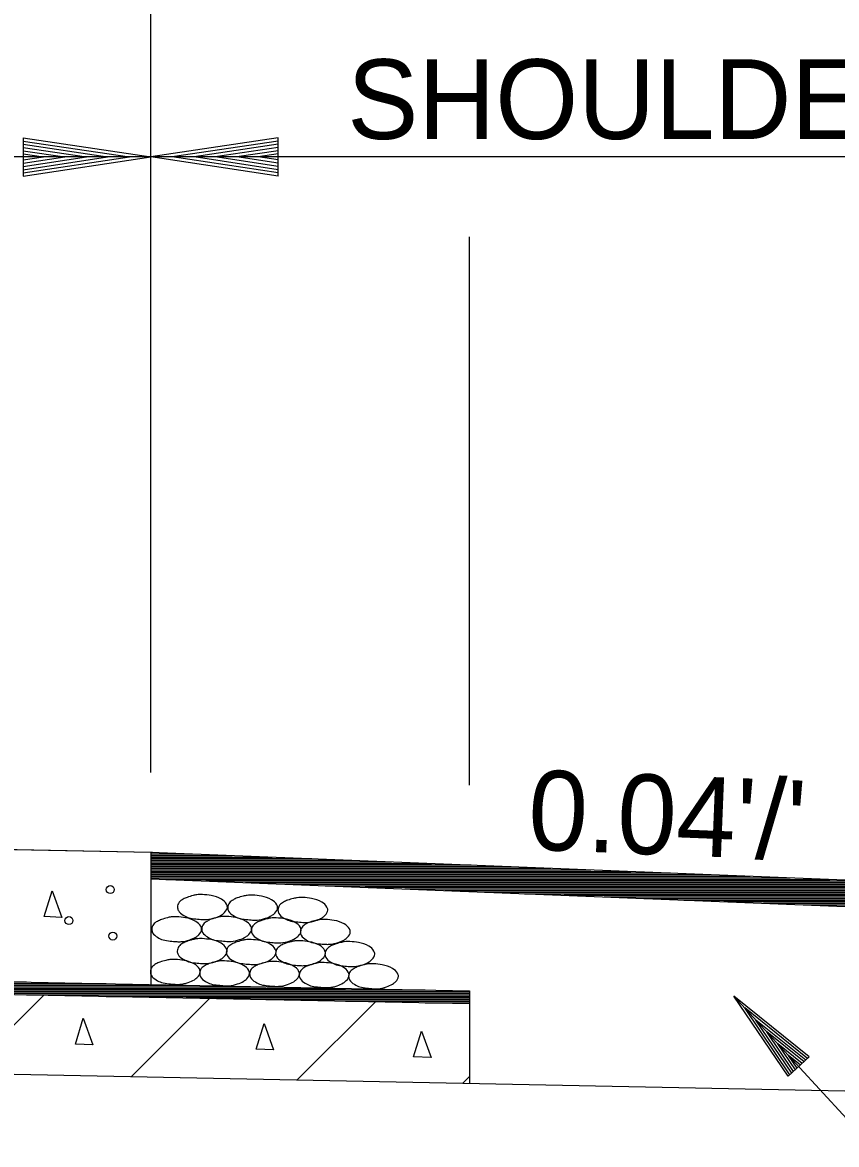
# Model space of a CAD drawing. Extents: x 60325 to 61047, y 53669 to 53767.
# Drawn here: x 60774.27 to 60779.38, y 53738.08 to 53745.12 of the extents above; entities that cross this region are included whole.
import ezdxf

# ---------------------------------------------------------------- set-up
doc = ezdxf.new("R2010")
doc.units = 0
doc.layers.add('R_Border', color=7, linetype='Continuous')
doc.layers.add('R_Border Prem', color=7, linetype='Continuous')

msp = doc.modelspace()

# ---------------------------------------------------------------- linework, layer by layer
at = {"layer": 'R_Border'}
for p, q in [((60775.0768, 53740.4116), (60775.0768, 53746.774)), ((60774.2768, 53744.3928), (60775.0768, 53744.2728)), ((60774.2768, 53744.3928), (60774.2768, 53744.1528)), ((60774.2768, 53744.3728), (60774.9432, 53744.2728)), ((60774.2768, 53744.3524), (60774.8056, 53744.2728)), ((60774.2768, 53744.3324), (60774.6724, 53744.2728)), ((60774.2768, 53744.3116), (60774.5368, 53744.2728)), ((60774.2768, 53744.2916), (60774.4032, 53744.2728)), ((60775.0768, 53744.2728), (60760.0768, 53744.2728)), ((60774.2768, 53744.1528), (60775.0768, 53744.2728)), ((60774.2768, 53744.2336), (60774.5368, 53744.2728)), ((60774.2768, 53744.1932), (60774.8056, 53744.2728)), ((60774.2768, 53744.1728), (60774.9432, 53744.2728)), ((60774.2768, 53744.2132), (60774.6724, 53744.2728)), ((60774.2768, 53744.254), (60774.4032, 53744.2728))]:
    msp.add_line(p, q, dxfattribs=at)
msp.add_lwpolyline([(60760.0768, 53740.2116), (60775.0768, 53739.9116)], dxfattribs=at)
at = {"layer": 'R_Border Prem'}
for p, q in [((60775.8768, 53744.3928), (60775.0768, 53744.2728)), ((60775.8768, 53744.3728), (60775.2104, 53744.2728)), ((60775.8768, 53744.1528), (60775.8768, 53744.3928)), ((60775.8768, 53744.3524), (60775.348, 53744.2728)), ((60775.8768, 53744.3324), (60775.4812, 53744.2728)), ((60775.8768, 53744.312), (60775.6168, 53744.2728)), ((60775.8768, 53744.2916), (60775.7504, 53744.2728)), ((60781.0768, 53744.2728), (60775.0768, 53744.2728)), ((60775.8768, 53744.1528), (60775.0768, 53744.2728)), ((60775.8768, 53744.1728), (60775.2104, 53744.2728)), ((60775.8768, 53744.1932), (60775.348, 53744.2728)), ((60775.8768, 53744.2132), (60775.4812, 53744.2728)), ((60775.8768, 53744.234), (60775.6168, 53744.2728)), ((60775.8768, 53744.254), (60775.7504, 53744.2728)), ((60777.0768, 53740.3316), (60777.0768, 53743.7728)), ((60760.0768, 53740.2116), (60775.0768, 53739.9116)), ((60775.0768, 53739.9116), (60781.0768, 53739.6716)), ((60775.0768, 53739.9116), (60775.0768, 53739.0816)), ((60775.0768, 53739.9111), (60775.0875, 53739.9111)), ((60775.0768, 53739.9011), (60775.3375, 53739.9011)), ((60775.0768, 53739.8911), (60775.5875, 53739.8911)), ((60775.0768, 53739.8811), (60775.8375, 53739.8811)), ((60775.0768, 53739.8711), (60776.0875, 53739.8711)), ((60775.0768, 53739.8611), (60776.3375, 53739.8611)), ((60775.0768, 53739.8511), (60776.5875, 53739.8511)), ((60775.0768, 53739.8411), (60776.8375, 53739.8411)), ((60775.0768, 53739.8311), (60777.0875, 53739.8311)), ((60775.0768, 53739.8211), (60777.3375, 53739.8211)), ((60775.0768, 53739.8111), (60777.5875, 53739.8111)), ((60775.0768, 53739.8011), (60777.8375, 53739.8011)), ((60775.0768, 53739.7911), (60778.0875, 53739.7911)), ((60775.0768, 53739.7811), (60778.3375, 53739.7811)), ((60775.0768, 53739.7711), (60778.5875, 53739.7711)), ((60775.0768, 53739.7611), (60778.8375, 53739.7611)), ((60775.0768, 53739.7511), (60779.0875, 53739.7511)), ((60775.0768, 53739.7449), (60781.0768, 53739.5049)), ((60775.171, 53739.7411), (60779.3375, 53739.7411)), ((60775.421, 53739.7311), (60779.5875, 53739.7311)), ((60775.671, 53739.7211), (60779.8375, 53739.7211)), ((60775.921, 53739.7111), (60780.0875, 53739.7111)), ((60776.171, 53739.7011), (60780.3375, 53739.7011)), ((60776.421, 53739.6911), (60780.5875, 53739.6911)), ((60776.671, 53739.6811), (60780.8375, 53739.6811)), ((60776.921, 53739.6711), (60781.0768, 53739.6711)), ((60777.171, 53739.6611), (60781.0768, 53739.6611)), ((60777.421, 53739.6511), (60781.0768, 53739.6511)), ((60777.671, 53739.6411), (60781.0768, 53739.6411)), ((60777.921, 53739.6311), (60781.0768, 53739.6311)), ((60778.171, 53739.6211), (60781.0768, 53739.6211)), ((60778.421, 53739.6111), (60781.0768, 53739.6111)), ((60778.671, 53739.6011), (60781.0768, 53739.6011)), ((60778.921, 53739.5911), (60781.0768, 53739.5911)), ((60779.171, 53739.5811), (60781.0768, 53739.5811)), ((60760.0768, 53739.3816), (60777.0768, 53739.0416)), ((60760.0768, 53739.3016), (60777.0768, 53738.9616)), ((60770.2976, 53739.0971), (60774.2976, 53739.0971)), ((60770.7976, 53739.0871), (60774.7976, 53739.0871)), ((60771.2976, 53739.0771), (60775.2976, 53739.0771)), ((60771.7976, 53739.0671), (60775.7976, 53739.0671)), ((60772.2976, 53739.0571), (60776.2976, 53739.0571)), ((60772.7976, 53739.0471), (60776.7976, 53739.0471)), ((60773.2976, 53739.0371), (60777.0768, 53739.0371)), ((60773.7976, 53739.0271), (60777.0768, 53739.0271)), ((60773.9158, 53738.5248), (60774.406, 53739.015)), ((60774.2976, 53739.0171), (60777.0768, 53739.0171)), ((60774.7976, 53739.0071), (60777.0768, 53739.0071)), ((60777.0768, 53739.0416), (60777.0768, 53738.4616)), ((60779.0759, 53738.5054), (60778.7356, 53739.0077)), ((60779.2083, 53738.6273), (60778.7356, 53739.0077)), ((60774.9557, 53738.504), (60775.4459, 53738.9942)), ((60775.2976, 53738.9971), (60777.0768, 53738.9971)), ((60775.7976, 53738.9871), (60777.0768, 53738.9871)), ((60775.9956, 53738.4832), (60776.4858, 53738.9734)), ((60776.2976, 53738.9771), (60777.0768, 53738.9771)), ((60776.7976, 53738.9671), (60777.0768, 53738.9671)), ((60779.0869, 53738.5155), (60778.8035, 53738.934)), ((60779.1973, 53738.6171), (60778.8035, 53738.934)), ((60760.0768, 53738.8016), (60789.8722, 53738.2056)), ((60779.186, 53738.6068), (60778.8734, 53738.8581)), ((60779.0982, 53738.5259), (60778.8734, 53738.8581)), ((60779.1092, 53738.5361), (60778.9411, 53738.7846)), ((60779.175, 53738.5966), (60778.9411, 53738.7846)), ((60779.1637, 53738.5863), (60779.01, 53738.7098)), ((60779.1207, 53738.5466), (60779.01, 53738.7098)), ((60779.0759, 53738.5054), (60779.2083, 53738.6273)), ((60779.1525, 53738.5759), (60779.0779, 53738.6361)), ((60779.1317, 53738.5568), (60779.0779, 53738.6361)), ((60777.0354, 53738.4624), (60777.0768, 53738.5037))]:
    msp.add_line(p, q, dxfattribs=at)
for points in [[(60774.4572, 53739.6685), (60774.5177, 53739.5025), (60774.4077, 53739.507), (60774.4572, 53739.6685)], [(60781.5545, 53736.5452), (60781.0037, 53736.5452), (60778.7356, 53739.0077)], [(60774.653, 53738.8695), (60774.7135, 53738.7035), (60774.6035, 53738.708), (60774.653, 53738.8695)], [(60775.7871, 53738.8371), (60775.8476, 53738.6711), (60775.7376, 53738.6756), (60775.7871, 53738.8371)], [(60776.7753, 53738.7885), (60776.8358, 53738.6225), (60776.7258, 53738.627), (60776.7753, 53738.7885)]]:
    msp.add_lwpolyline(points, dxfattribs=at)
for centre in [(60774.8223, 53739.6769), (60774.5631, 53739.4825), (60774.8385, 53739.3853)]:
    msp.add_circle(centre, 0.025, dxfattribs=at)
for points in [[(60775.4007, 53739.6456), (60775.4557, 53739.6394), (60775.5195, 53739.6169), (60775.552, 53739.5856), (60775.557, 53739.5669), (60775.5395, 53739.5331), (60775.5207, 53739.5181), (60775.482, 53739.5006), (60775.4282, 53739.4894), (60775.4007, 53739.4894), (60775.3595, 53739.4931), (60775.3145, 53739.5006), (60775.2807, 53739.5169), (60775.2495, 53739.5456), (60775.2445, 53739.5669), (60775.2545, 53739.5969), (60775.2795, 53739.6169), (60775.3045, 53739.6281), (60775.342, 53739.6394), (60775.3657, 53739.6444), (60775.4007, 53739.6456)], [(60775.7158, 53739.6419), (60775.7708, 53739.6357), (60775.8346, 53739.6132), (60775.8671, 53739.5819), (60775.8721, 53739.5632), (60775.8546, 53739.5294), (60775.8358, 53739.5144), (60775.7971, 53739.4969), (60775.7433, 53739.4857), (60775.7158, 53739.4857), (60775.6746, 53739.4894), (60775.6296, 53739.4969), (60775.5958, 53739.5132), (60775.5646, 53739.5419), (60775.5596, 53739.5632), (60775.5696, 53739.5932), (60775.5946, 53739.6132), (60775.6196, 53739.6244), (60775.6571, 53739.6357), (60775.6808, 53739.6407), (60775.7158, 53739.6419)], [(60776.0309, 53739.6273), (60776.0859, 53739.621), (60776.1496, 53739.5985), (60776.1821, 53739.5673), (60776.1871, 53739.5485), (60776.1696, 53739.5148), (60776.1509, 53739.4998), (60776.1121, 53739.4823), (60776.0584, 53739.471), (60776.0309, 53739.471), (60775.9896, 53739.4748), (60775.9446, 53739.4823), (60775.9109, 53739.4985), (60775.8796, 53739.5273), (60775.8746, 53739.5485), (60775.8846, 53739.5785), (60775.9096, 53739.5985), (60775.9346, 53739.6098), (60775.9721, 53739.621), (60775.9959, 53739.626), (60776.0309, 53739.6273)], [(60775.2396, 53739.5064), (60775.2946, 53739.5001), (60775.3583, 53739.4776), (60775.3908, 53739.4464), (60775.3958, 53739.4276), (60775.3783, 53739.3939), (60775.3596, 53739.3789), (60775.3208, 53739.3614), (60775.2671, 53739.3501), (60775.2396, 53739.3501), (60775.1983, 53739.3539), (60775.1533, 53739.3614), (60775.1196, 53739.3776), (60775.0883, 53739.4064), (60775.0833, 53739.4276), (60775.0933, 53739.4576), (60775.1183, 53739.4776), (60775.1433, 53739.4889), (60775.1808, 53739.5001), (60775.2046, 53739.5051), (60775.2396, 53739.5064)], [(60775.5528, 53739.5082), (60775.6078, 53739.502), (60775.6715, 53739.4795), (60775.704, 53739.4482), (60775.709, 53739.4295), (60775.6915, 53739.3957), (60775.6728, 53739.3807), (60775.634, 53739.3632), (60775.5803, 53739.352), (60775.5528, 53739.352), (60775.5115, 53739.3557), (60775.4665, 53739.3632), (60775.4328, 53739.3795), (60775.4015, 53739.4082), (60775.3965, 53739.4295), (60775.4065, 53739.4595), (60775.4315, 53739.4795), (60775.4565, 53739.4907), (60775.494, 53739.502), (60775.5178, 53739.507), (60775.5528, 53739.5082)], [(60775.8642, 53739.4991), (60775.9192, 53739.4928), (60775.9829, 53739.4703), (60776.0154, 53739.4391), (60776.0204, 53739.4203), (60776.0029, 53739.3866), (60775.9842, 53739.3716), (60775.9454, 53739.3541), (60775.8917, 53739.3428), (60775.8642, 53739.3428), (60775.8229, 53739.3466), (60775.7779, 53739.3541), (60775.7442, 53739.3703), (60775.7129, 53739.3991), (60775.7079, 53739.4203), (60775.7179, 53739.4503), (60775.7429, 53739.4703), (60775.7679, 53739.4816), (60775.8054, 53739.4928), (60775.8292, 53739.4978), (60775.8642, 53739.4991)], [(60776.1719, 53739.4899), (60776.2269, 53739.4837), (60776.2906, 53739.4612), (60776.3231, 53739.4299), (60776.3281, 53739.4112), (60776.3106, 53739.3774), (60776.2919, 53739.3624), (60776.2531, 53739.3449), (60776.1994, 53739.3337), (60776.1719, 53739.3337), (60776.1306, 53739.3374), (60776.0856, 53739.3449), (60776.0519, 53739.3612), (60776.0206, 53739.3899), (60776.0156, 53739.4112), (60776.0256, 53739.4412), (60776.0506, 53739.4612), (60776.0756, 53739.4724), (60776.1131, 53739.4837), (60776.1369, 53739.4887), (60776.1719, 53739.4899)], [(60775.3989, 53739.369), (60775.4539, 53739.3628), (60775.5177, 53739.3403), (60775.5502, 53739.309), (60775.5552, 53739.2903), (60775.5377, 53739.2565), (60775.5189, 53739.2415), (60775.4802, 53739.224), (60775.4264, 53739.2128), (60775.3989, 53739.2128), (60775.3577, 53739.2165), (60775.3127, 53739.224), (60775.2789, 53739.2403), (60775.2477, 53739.269), (60775.2427, 53739.2903), (60775.2527, 53739.3203), (60775.2777, 53739.3403), (60775.3027, 53739.3515), (60775.3402, 53739.3628), (60775.3639, 53739.3678), (60775.3989, 53739.369)], [(60775.7066, 53739.3635), (60775.7616, 53739.3573), (60775.8254, 53739.3348), (60775.8579, 53739.3035), (60775.8629, 53739.2848), (60775.8454, 53739.251), (60775.8266, 53739.236), (60775.7879, 53739.2185), (60775.7341, 53739.2073), (60775.7066, 53739.2073), (60775.6654, 53739.211), (60775.6204, 53739.2185), (60775.5866, 53739.2348), (60775.5554, 53739.2635), (60775.5504, 53739.2848), (60775.5604, 53739.3148), (60775.5854, 53739.3348), (60775.6104, 53739.346), (60775.6479, 53739.3573), (60775.6716, 53739.3623), (60775.7066, 53739.3635)], [(60776.0162, 53739.3562), (60776.0712, 53739.3499), (60776.135, 53739.3274), (60776.1675, 53739.2962), (60776.1725, 53739.2774), (60776.155, 53739.2437), (60776.1362, 53739.2287), (60776.0975, 53739.2112), (60776.0437, 53739.1999), (60776.0162, 53739.1999), (60775.975, 53739.2037), (60775.93, 53739.2112), (60775.8962, 53739.2274), (60775.865, 53739.2562), (60775.86, 53739.2774), (60775.87, 53739.3074), (60775.895, 53739.3274), (60775.92, 53739.3387), (60775.9575, 53739.3499), (60775.9812, 53739.3549), (60776.0162, 53739.3562)], [(60776.3258, 53739.3507), (60776.3808, 53739.3444), (60776.4445, 53739.3219), (60776.477, 53739.2907), (60776.482, 53739.2719), (60776.4645, 53739.2382), (60776.4458, 53739.2232), (60776.407, 53739.2057), (60776.3533, 53739.1944), (60776.3258, 53739.1944), (60776.2845, 53739.1982), (60776.2395, 53739.2057), (60776.2058, 53739.2219), (60776.1745, 53739.2507), (60776.1695, 53739.2719), (60776.1795, 53739.3019), (60776.2045, 53739.3219), (60776.2295, 53739.3332), (60776.267, 53739.3444), (60776.2908, 53739.3494), (60776.3258, 53739.3507)], [(60775.2304, 53739.239), (60775.2854, 53739.2327), (60775.3492, 53739.2102), (60775.3817, 53739.179), (60775.3867, 53739.1602), (60775.3692, 53739.1265), (60775.3504, 53739.1115), (60775.3117, 53739.094), (60775.2579, 53739.0827), (60775.2304, 53739.0827), (60775.1892, 53739.0865), (60775.1442, 53739.094), (60775.1104, 53739.1102), (60775.0792, 53739.139), (60775.0742, 53739.1602), (60775.0842, 53739.1902), (60775.1092, 53739.2102), (60775.1342, 53739.2215), (60775.1717, 53739.2327), (60775.1954, 53739.2377), (60775.2304, 53739.239)], [(60775.54, 53739.2298), (60775.595, 53739.2236), (60775.6587, 53739.2011), (60775.6912, 53739.1698), (60775.6962, 53739.1511), (60775.6787, 53739.1173), (60775.66, 53739.1023), (60775.6212, 53739.0848), (60775.5675, 53739.0736), (60775.54, 53739.0736), (60775.4987, 53739.0773), (60775.4537, 53739.0848), (60775.42, 53739.1011), (60775.3887, 53739.1298), (60775.3837, 53739.1511), (60775.3937, 53739.1811), (60775.4187, 53739.2011), (60775.4437, 53739.2123), (60775.4812, 53739.2236), (60775.505, 53739.2286), (60775.54, 53739.2298)], [(60775.8532, 53739.2261), (60775.9082, 53739.2199), (60775.9719, 53739.1974), (60776.0044, 53739.1661), (60776.0094, 53739.1474), (60775.9919, 53739.1136), (60775.9732, 53739.0986), (60775.9344, 53739.0811), (60775.8807, 53739.0699), (60775.8532, 53739.0699), (60775.8119, 53739.0736), (60775.7669, 53739.0811), (60775.7332, 53739.0974), (60775.7019, 53739.1261), (60775.6969, 53739.1474), (60775.7069, 53739.1774), (60775.7319, 53739.1974), (60775.7569, 53739.2086), (60775.7944, 53739.2199), (60775.8182, 53739.2249), (60775.8532, 53739.2261)], [(60776.1646, 53739.2188), (60776.2196, 53739.2126), (60776.2833, 53739.1901), (60776.3158, 53739.1588), (60776.3208, 53739.1401), (60776.3033, 53739.1063), (60776.2846, 53739.0913), (60776.2458, 53739.0738), (60776.1921, 53739.0626), (60776.1646, 53739.0626), (60776.1233, 53739.0663), (60776.0783, 53739.0738), (60776.0446, 53739.0901), (60776.0133, 53739.1188), (60776.0083, 53739.1401), (60776.0183, 53739.1701), (60776.0433, 53739.1901), (60776.0683, 53739.2013), (60776.1058, 53739.2126), (60776.1296, 53739.2176), (60776.1646, 53739.2188)], [(60776.4741, 53739.2115), (60776.5291, 53739.2052), (60776.5929, 53739.1827), (60776.6254, 53739.1515), (60776.6304, 53739.1327), (60776.6129, 53739.099), (60776.5941, 53739.084), (60776.5554, 53739.0665), (60776.5016, 53739.0552), (60776.4741, 53739.0552), (60776.4329, 53739.059), (60776.3879, 53739.0665), (60776.3541, 53739.0827), (60776.3229, 53739.1115), (60776.3179, 53739.1327), (60776.3279, 53739.1627), (60776.3529, 53739.1827), (60776.3779, 53739.194), (60776.4154, 53739.2052), (60776.4391, 53739.2102), (60776.4741, 53739.2115)]]:
    msp.add_spline(points, degree=3, dxfattribs=at)

# ---------------------------------------------------------------- texts
msp.add_text('SHOULDER', height=0.5, dxfattribs=at).set_placement((60776.3093, 53744.3856))
msp.add_text("0.04'/'", height=0.5, rotation=357.70939, dxfattribs=at).set_placement((60777.4375, 53739.9291))

doc.saveas('drawing.dxf')
